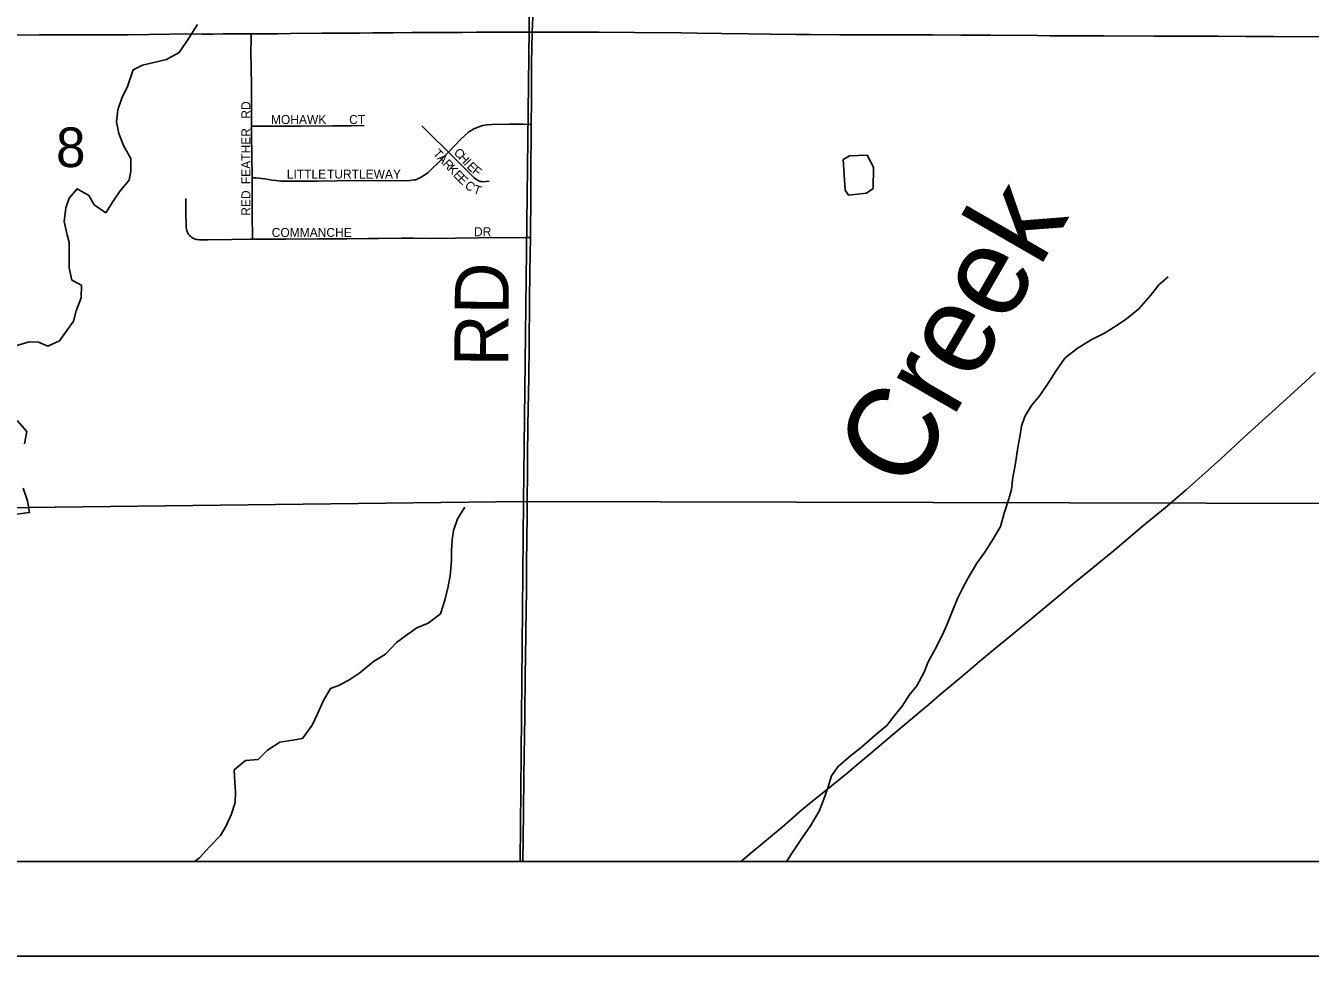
# Model space of a CAD drawing. Extents: x 0 to 1391, y -24 to 440.
# Drawn here: x 416.5 to 443.6, y 280 to 299.64 of the extents above; entities that cross this region are included whole.
import ezdxf

# ---------------------------------------------------------------- set-up
doc = ezdxf.new("R2010")
doc.units = 0
for name, color, linetype in [('GM_X_County_Road', 7, 'Continuous'), ('GM_X_Minor_Lake', 7, 'Continuous'), ('GM_X_Minor_River', 7, 'Continuous'), ('GM_X_Minor_River_Text', 7, 'Continuous'), ('GM_X_Section', 7, 'Continuous'), ('GM_X_Section_Text', 7, 'Continuous'), ('GM_X_Township', 7, 'Continuous'), ('GM_X_Township_Road', 7, 'Continuous'), ('GM_X_Township_Road_Text', 7, 'Continuous'), ('GM_X_Township_Subdivision', 7, 'Continuous'), ('GM_X_Township_Subdivision_Text', 7, 'Continuous'), ('SH_Data', 7, 'Continuous')]:
    doc.layers.add(name, color=color, linetype=linetype)

msp = doc.modelspace()

# ---------------------------------------------------------------- linework, layer by layer
at = {"layer": 'GM_X_County_Road'}
msp.add_lwpolyline([(431.588, 282), (432.256, 282.556), (432.455, 282.725), (432.868, 283.083), (433.068, 283.25), (433.31, 283.444), (433.677, 283.74), (433.82, 283.86), (434.02, 284.027), (434.315, 284.275), (434.506, 284.434), (434.78, 284.667), (435.218, 285.034), (435.387, 285.18), (435.549, 285.316), (435.776, 285.509), (436.155, 285.83), (436.375, 286.012), (436.623, 286.22), (436.918, 286.467), (437.341, 286.814), (437.819, 287.21), (438.362, 287.665), (438.639, 287.896), (439.014, 288.202), (439.474, 288.582), (440.045, 289.062), (440.544, 289.473), (440.979, 289.844), (441.249, 290.083), (441.709, 290.501), (442.122, 290.878), (442.589, 291.307), (442.865, 291.557), (443.499, 292.134), (443.699, 292.319)], dxfattribs=at)
at = {"layer": 'GM_X_Minor_Lake'}
for points in [[(434.378, 296.207), (434.386, 296.657), (434.251, 296.906), (433.878, 296.897), (433.746, 296.817)], [(433.746, 296.817), (433.784, 296.168), (433.856, 296.066), (434.238, 296.106), (434.378, 296.207)]]:
    msp.add_lwpolyline(points, dxfattribs=at)
at = {"layer": 'GM_X_Minor_River'}
for points in [[(418.649, 298.36), (418.77, 298.709), (418.962, 298.804), (419.23, 298.868), (419.474, 298.925), (419.736, 299.072), (419.939, 299.379), (420.126, 299.664)], [(417.471, 294.268), (417.42, 294.529), (417.42, 294.766), (417.416, 295.063), (417.369, 295.256), (417.31, 295.51), (417.35, 295.798), (417.418, 296.001), (417.585, 296.194), (417.831, 296.055), (417.945, 295.86), (418.19, 295.691), (418.343, 295.938), (418.495, 296.153), (418.686, 296.383), (418.715, 296.573), (418.717, 296.839), (418.567, 297.112), (418.462, 297.367), (418.418, 297.613), (418.442, 297.864), (418.526, 298.112), (418.649, 298.36)], [(432.55, 282), (432.684, 282.205), (432.877, 282.503), (433.053, 282.756), (433.239, 283.062), (433.339, 283.318), (433.423, 283.559), (433.501, 283.807), (433.637, 284.008), (433.903, 284.228), (434.122, 284.41), (434.42, 284.667), (434.663, 284.872), (434.838, 285.086), (434.989, 285.279), (435.134, 285.511), (435.301, 285.71), (435.455, 285.995), (435.539, 286.213), (435.685, 286.482), (435.832, 286.774), (435.956, 287.044), (436.048, 287.293), (436.164, 287.563), (436.263, 287.766), (436.376, 287.975), (436.563, 288.296), (436.73, 288.527), (436.915, 288.818), (437.061, 289.072), (437.148, 289.374), (437.241, 289.652), (437.294, 289.849), (437.326, 290.115), (437.373, 290.357), (437.431, 290.736), (437.47, 290.964), (437.508, 291.191), (437.576, 291.395), (437.721, 291.626), (437.896, 291.833), (438.081, 292.116), (438.233, 292.347), (438.418, 292.623), (438.683, 292.827), (438.978, 293.007), (439.257, 293.149), (439.522, 293.323), (439.724, 293.453), (439.982, 293.665), (440.228, 293.946), (440.403, 294.168), (440.599, 294.337)], [(416.313, 292.891), (416.574, 292.966), (416.771, 292.959), (416.966, 292.875), (417.213, 292.989), (417.357, 293.189), (417.509, 293.405), (417.563, 293.624), (417.671, 293.895), (417.68, 294.162), (417.471, 294.268)], [(416.476, 290.819), (416.523, 291.076), (416.318, 291.305)], [(416.309, 289.33), (416.584, 289.366), (416.54, 289.611), (416.45, 289.881)], [(420.06, 282), (420.167, 282.075), (420.38, 282.312), (420.609, 282.547), (420.73, 282.757), (420.837, 282.989), (420.922, 283.245), (420.923, 283.474), (420.914, 283.665), (420.901, 283.933), (421.136, 284.13), (421.403, 284.151), (421.6, 284.35), (421.864, 284.523), (422.139, 284.559), (422.338, 284.598), (422.546, 284.88), (422.653, 285.12), (422.785, 285.398), (422.93, 285.652), (423.123, 285.721), (423.34, 285.843), (423.55, 285.98), (423.84, 286.222), (424.089, 286.38), (424.325, 286.624), (424.56, 286.798), (424.754, 286.929), (424.994, 287.034), (425.251, 287.231), (425.345, 287.517), (425.407, 287.774), (425.454, 288.032), (425.481, 288.344), (425.481, 288.557), (425.496, 288.793), (425.526, 288.99), (425.611, 289.231), (425.764, 289.478)]]:
    msp.add_lwpolyline(points, dxfattribs=at)
at = {"layer": 'GM_X_Section'}
for p, q in [((408.377, 282), (426.931, 282)), ((426.931, 282), (447.109, 282))]:
    msp.add_line(p, q, dxfattribs=at)
for points in [[(427.24, 309.578), (427.002, 289.599), (407.817, 289.368), (407.8, 309.486)], [(447.244, 309.439), (447.159, 289.547), (427.002, 289.599), (427.24, 309.578)]]:
    msp.add_lwpolyline(points, close=True, dxfattribs=at)
for points in [[(426.931, 282), (427.002, 289.599), (407.817, 289.368), (408.377, 282)], [(447.109, 282), (447.159, 289.547), (427.002, 289.599), (426.931, 282)]]:
    msp.add_lwpolyline(points, dxfattribs=at)
at = {"layer": 'GM_X_Township'}
msp.add_line((347.795, 282), (465.978, 282), dxfattribs=at)
at = {"layer": 'GM_X_Township_Road'}
for points in [[(427.186, 299.506), (427.199, 299.83)], [(416.243, 299.443), (416.79, 299.45), (417.435, 299.45), (417.806, 299.448), (418.141, 299.448), (418.364, 299.446), (418.661, 299.447), (419.096, 299.451), (419.539, 299.46), (419.865, 299.466), (420.225, 299.464), (420.449, 299.463), (420.659, 299.466), (421.007, 299.469), (421.254, 299.47)], [(421.254, 299.47), (421.404, 299.47), (421.827, 299.47), (422.087, 299.473), (422.746, 299.48), (423.143, 299.483), (423.54, 299.484), (423.826, 299.486), (424.249, 299.492), (424.646, 299.496), (425.006, 299.498), (425.403, 299.497), (425.714, 299.5), (426.012, 299.501), (426.446, 299.504), (426.98, 299.506), (427.186, 299.506)], [(427.165, 297.558), (427.17, 298.052), (427.171, 298.55), (427.171, 298.849), (427.186, 299.506)], [(427.186, 299.506), (427.956, 299.506), (428.595, 299.506), (429.34, 299.495), (430.335, 299.486), (430.67, 299.481), (431.18, 299.474), (431.739, 299.467), (432.211, 299.461), (432.758, 299.453), (433.056, 299.453), (433.665, 299.45), (434.2, 299.446), (434.473, 299.445), (435.007, 299.444), (435.629, 299.447), (436.225, 299.443), (436.859, 299.44), (437.841, 299.431), (438.102, 299.429), (438.648, 299.427), (439.245, 299.425), (440.301, 299.42), (440.898, 299.419), (441.656, 299.416), (442.24, 299.413), (442.824, 299.411), (443.855, 299.407)], [(427.147, 295.169), (427.15, 295.332), (427.154, 295.929), (427.156, 296.786), (427.161, 297.221), (427.165, 297.558)], [(426.988, 282), (427.001, 283.019), (427.01, 283.814), (427.028, 285.069), (427.04, 285.952), (427.044, 286.312), (427.049, 286.809), (427.058, 287.331), (427.066, 287.691), (427.068, 288.3), (427.078, 289.306), (427.086, 290.524), (427.095, 291.207), (427.111, 292.214), (427.118, 292.909), (427.129, 293.829), (427.136, 294.45), (427.147, 295.169)]]:
    msp.add_lwpolyline(points, dxfattribs=at)
at = {"layer": 'GM_X_Township_Subdivision'}
for points in [[(421.261, 297.519), (421.261, 297.587), (421.264, 298.072), (421.262, 298.37), (421.256, 298.755), (421.253, 299.065), (421.254, 299.363), (421.254, 299.47)], [(425.416, 296.972), (425.673, 297.24), (425.774, 297.332), (425.851, 297.397), (425.912, 297.437), (425.957, 297.462), (426.013, 297.488), (426.083, 297.516), (426.143, 297.534), (426.227, 297.549), (426.338, 297.558), (426.698, 297.563), (426.996, 297.56), (427.165, 297.558)], [(421.261, 297.519), (421.409, 297.519), (421.906, 297.52), (422.304, 297.523), (422.976, 297.528), (423.374, 297.53), (423.638, 297.532)], [(421.275, 296.431), (421.268, 296.905), (421.264, 297.327), (421.261, 297.519)], [(425.416, 296.972), (425.315, 297.074), (425.113, 297.277), (424.9, 297.486), (424.858, 297.529)], [(421.275, 296.431), (421.355, 296.427), (421.417, 296.422), (421.475, 296.416), (421.544, 296.408), (421.62, 296.395), (421.695, 296.382), (421.778, 296.37), (421.884, 296.362), (422.087, 296.359), (422.659, 296.359), (423.069, 296.363), (423.652, 296.37), (424.311, 296.369), (424.602, 296.375), (424.652, 296.378), (424.695, 296.384), (424.726, 296.39), (424.747, 296.397), (424.771, 296.407), (424.812, 296.426), (424.845, 296.445), (424.886, 296.47), (424.939, 296.505), (424.99, 296.545), (425.038, 296.588), (425.097, 296.645), (425.166, 296.712), (425.416, 296.972)], [(426.277, 296.361), (426.143, 296.347), (426.116, 296.349), (426.093, 296.353), (426.075, 296.359), (426.055, 296.367), (426.035, 296.378), (426.01, 296.394), (425.964, 296.431), (425.846, 296.541), (425.416, 296.972)], [(421.286, 295.133), (421.284, 295.254), (421.279, 295.564), (421.279, 295.775), (421.277, 295.986), (421.275, 296.431)], [(419.882, 295.99), (419.882, 295.842), (419.882, 295.655), (419.883, 295.467), (419.885, 295.411), (419.887, 295.383), (419.89, 295.356), (419.894, 295.336), (419.899, 295.315), (419.905, 295.298), (419.912, 295.28), (419.923, 295.259), (419.938, 295.234), (419.957, 295.213), (419.985, 295.189), (420.008, 295.171), (420.036, 295.153), (420.057, 295.144), (420.08, 295.136), (420.106, 295.131), (420.134, 295.126), (420.168, 295.124), (420.342, 295.122), (420.851, 295.126), (421.236, 295.132), (421.286, 295.133)], [(421.286, 295.133), (421.633, 295.136), (421.98, 295.135), (422.663, 295.144), (423.283, 295.142), (423.73, 295.149), (423.953, 295.152), (424.425, 295.154), (424.673, 295.156), (425.033, 295.152), (425.567, 295.154), (426.051, 295.16), (427.045, 295.168), (427.147, 295.169)]]:
    msp.add_lwpolyline(points, dxfattribs=at)
at = {"layer": 'SH_Data'}
for p, q in [((342, 282), (478, 282)), ((340, 280), (480, 280))]:
    msp.add_line(p, q, dxfattribs=at)

# ---------------------------------------------------------------- texts
at = {"layer": 'GM_X_Minor_River_Text'}
msp.add_text('Creek', height=1.8935, rotation=60.0109, dxfattribs=at).set_placement((435.139, 289.756))
at = {"layer": 'GM_X_Section_Text'}
msp.add_text('8', height=0.837, rotation=0, dxfattribs=at).set_placement((417.14, 296.656))
at = {"layer": 'GM_X_Township_Road_Text'}
msp.add_text('RD', height=1.1364, rotation=89.5167, dxfattribs=at).set_placement((426.677, 292.443))
at = {"layer": 'GM_X_Township_Subdivision_Text'}
for s, height, rotation, p in [('RD', 0.1894, 90, (421.24, 297.679)), ('MOHAWK', 0.1894, 0, (421.674, 297.565)), ('CT', 0.1894, 0, (423.324, 297.565)), ('FEATHER', 0.1894, 90, (421.24, 296.296)), ('T', 0.189, 313.3193, (425.079, 296.93)), ('C', 0.189, 312.5008, (425.517, 296.953)), ('A', 0.189, 313.3074, (425.171, 296.833)), ('R', 0.189, 313.3249, (425.285, 296.712)), ('H', 0.189, 312.4957, (425.618, 296.843)), ('I', 0.189, 312.5109, (425.731, 296.72)), ('E', 0.189, 315.4734, (425.794, 296.651)), ('LITTLE', 0.1894, 0, (422.007, 296.415)), ('TURTLE', 0.1894, 0, (422.857, 296.415)), ('WAY', 0.1894, 0, (423.84, 296.415)), ('K', 0.189, 313.4068, (425.388, 296.603)), ('E', 0.189, 313.9277, (425.504, 296.48)), ('E', 0.189, 315.5447, (425.601, 296.38)), ('F', 0.189, 321.2831, (425.905, 296.543)), ('C', 0.189, 320.2466, (425.745, 296.241)), ('T', 0.189, 341.187, (425.926, 296.109)), ('RED', 0.1894, 90, (421.24, 295.629)), ('DR', 0.1894, 0, (425.957, 295.198)), ('COMMANCHE', 0.1894, 0, (421.69, 295.182))]:
    msp.add_text(s, height=height, rotation=rotation, dxfattribs=at).set_placement(p)

doc.saveas('drawing.dxf')
